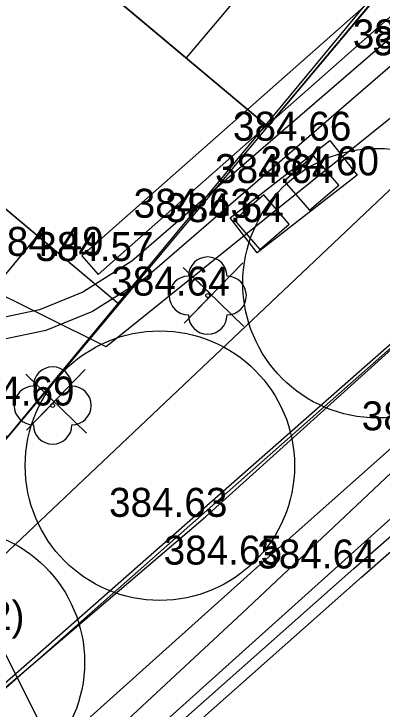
# Model space of a CAD drawing. Extents: x -438233 to -437334, y -1133133 to -1132623.
# Drawn here: x -438075.74 to -438066.2, y -1133013.03 to -1132995.04 of the extents above; entities that cross this region are included whole.
import ezdxf

# ---------------------------------------------------------------- set-up
doc = ezdxf.new("R2010")
doc.units = 0
for name, color, linetype in [('Vrstva 1', 7, 'Continuous'), ('Vrstva 10', 7, 'Continuous'), ('Vrstva 11', 7, 'Continuous'), ('Vrstva 22', 7, 'Continuous'), ('Vrstva 26', 7, 'Continuous'), ('Vrstva 3', 7, 'Continuous'), ('Vrstva 40', 7, 'Continuous'), ('Vrstva 50', 7, 'Continuous'), ('Vrstva 53', 7, 'Continuous'), ('Vrstva 55', 7, 'Continuous'), ('Vrstva 7', 7, 'Continuous'), ('Vrstva 9', 7, 'Continuous')]:
    doc.layers.add(name, color=color, linetype=linetype)

msp = doc.modelspace()

# ---------------------------------------------------------------- linework, layer by layer
at = {"layer": 'Vrstva 1'}
for p, q in [((-438094.467, -1132976.751), (-438069.171, -1132997.943)), ((-438098.32, -1132981.35), (-438073.024, -1133002.543)), ((-438068.389, -1132992.728), (-438071.279, -1132996.177)), ((-438066.287, -1132994.502), (-438076.556, -1133006.759)), ((-438067.569, -1132998.318), (-438067.569, -1132998.318)), ((-438066.854, -1132999.215), (-438066.854, -1132999.215)), ((-438068.034, -1132999.416), (-438068.034, -1132999.416)), ((-438070.142, -1133000.313), (-438070.142, -1133000.313)), ((-438069.32, -1133000.427), (-438069.32, -1133000.427)), ((-438075.132, -1133000.777), (-438078.022, -1133004.226)), ((-438073.986, -1133001.3), (-438073.986, -1133001.3)), ((-438072.69, -1133001.433), (-438072.69, -1133001.433)), ((-438070.722, -1133002.328), (-438070.722, -1133002.328)), ((-438074.741, -1133005.174), (-438074.741, -1133005.174)), ((-438070.78, -1133008.056), (-438070.78, -1133008.056)), ((-438069.364, -1133009.292), (-438069.364, -1133009.292)), ((-438066.939, -1133009.393), (-438066.939, -1133009.393))]:
    msp.add_line(p, q, dxfattribs=at)
at = {"layer": 'Vrstva 10'}
msp.add_lwpolyline([(-438035.457, -1132968.667), (-438040.579, -1132973.124), (-438048.857, -1132980.452), (-438065.053, -1132994.849), (-438072.69, -1133001.433), (-438073.961, -1133002.24), (-438075.077, -1133002.697), (-438076.272, -1133002.948)], dxfattribs=at)
at = {"layer": 'Vrstva 11'}
for points in [[(-438079.851, -1133001.541), (-438081.143, -1133003.836), (-438082.651, -1133014.98), (-438080.295, -1133016.157), (-438070.78, -1133008.056), (-438059.123, -1132997.555), (-438044.087, -1132984.346), (-438028.394, -1132970.577), (-438016.298, -1132960.009), (-438006.567, -1132951.363)], [(-438080.927, -1133019.451), (-438077.139, -1133016.254), (-438069.364, -1133009.292), (-438057.759, -1132998.987), (-438043.045, -1132985.96), (-438027.231, -1132972.034), (-438013.435, -1132960.019)], [(-438073.986, -1133001.3), (-438049.447, -1132979.638), (-438041.292, -1132972.525), (-438035.024, -1132966.82)], [(-438073.562, -1133001.78), (-438065.335, -1132994.517)], [(-438073.986, -1133001.3), (-438073.562, -1133001.78)]]:
    msp.add_lwpolyline(points, dxfattribs=at)
msp.add_lwpolyline([(-438070.142, -1133000.313), (-438067.557, -1132998.309), (-438066.854, -1132999.215), (-438069.439, -1133001.219)], close=True, dxfattribs=at)
at = {"layer": 'Vrstva 22'}
for centre in [(-438070.722, -1133002.328), (-438074.741, -1133005.174)]:
    msp.add_circle(centre, 0.05, dxfattribs=at)
for centre, start, end in [((-438070.722, -1133001.828), 0, 180), ((-438071.222, -1133002.328), 90, 270), ((-438070.222, -1133002.328), 270, 90), ((-438070.722, -1133002.828), 180, 0), ((-438074.741, -1133004.674), 0, 180), ((-438075.241, -1133005.174), 90, 270), ((-438074.241, -1133005.174), 270, 90), ((-438074.741, -1133005.674), 180, 0)]:
    msp.add_arc(centre, 0.5, start, end, dxfattribs=at)
at = {"layer": 'Vrstva 26'}
for points in [[(-438067.982, -1132998.711), (-438068.739, -1132999.364), (-438068.086, -1133000.121), (-438067.329, -1132999.468)], [(-438069.268, -1132999.722), (-438070.025, -1133000.375), (-438069.372, -1133001.132), (-438068.615, -1133000.479)]]:
    msp.add_lwpolyline(points, close=True, dxfattribs=at)
at = {"layer": 'Vrstva 40'}
for points in [[(-438006.567, -1132951.363), (-438080.295, -1133016.157), (-438085.207, -1133012.071), (-438080.546, -1133006.803), (-438077.182, -1133006.231), (-438076.556, -1133006.759), (-438075.914, -1133005.992), (-438066.402, -1132994.506), (-438073.034, -1132988.817), (-438072.353, -1132988.023), (-438069.665, -1132990.252), (-438068.287, -1132988.606), (-438065.604, -1132990.854), (-438063.799, -1132988.701), (-438061.117, -1132990.948), (-438050.796, -1132978.629), (-438047.72, -1132977.59), (-438045.204, -1132976.394), (-438042.678, -1132974.884), (-438040.928, -1132973.634), (-438039.59, -1132972.514), (-438037.876, -1132970.87), (-438035.397, -1132967.806), (-438020.007, -1132954.124)], [(-438069.816, -1133001.479), (-438071.336, -1133003.045), (-438070.625, -1133002.312), (-438071.358, -1133001.601), (-438069.785, -1133003.126)], [(-438073.895, -1133004.243), (-438075.415, -1133005.81), (-438074.704, -1133005.077), (-438075.437, -1133004.366), (-438073.864, -1133005.891)]]:
    msp.add_lwpolyline(points, dxfattribs=at)
for centre in [(-438066.325, -1133002.007), (-438071.963, -1133006.731), (-438077.403, -1133011.819)]:
    msp.add_circle(centre, 3.489, dxfattribs=at)
at = {"layer": 'Vrstva 50'}
for points in [[(-438091.577, -1132973.302), (-438066.273, -1132994.5), (-438069.163, -1132997.95), (-438094.467, -1132976.751)], [(-438098.32, -1132981.35), (-438073.025, -1133002.541), (-438075.915, -1133005.991), (-438101.21, -1132984.8)]]:
    msp.add_lwpolyline(points, close=True, dxfattribs=at)
at = {"layer": 'Vrstva 53'}
for points in [[(-438082.34, -1133022.27), (-438082.4, -1133022.17), (-438081.23, -1133020.54), (-438076.87, -1133017.08), (-438069.83, -1133010.55), (-438064.49, -1133005.53), (-438059.58, -1133001.78), (-438053.45, -1132996.74), (-438044, -1132988.47), (-438035.57, -1132981.06), (-438029.47, -1132975.65), (-438020.01, -1132967.31), (-438013.46, -1132961.68), (-438012.29, -1132959.83), (-438009.79, -1132957.66), (-438009.76, -1132957.6), (-438007.47, -1132956.33), (-438007.65, -1132955.49), (-438008.56, -1132952.65)], [(-438080.228, -1133025.09), (-438082.04, -1133022.81), (-438081.87, -1133021.95), (-438073.76, -1133015.09), (-438028.25, -1132974.2), (-438011.87, -1132960.69), (-438014.77, -1132957.4)]]:
    msp.add_lwpolyline(points, dxfattribs=at)
at = {"layer": 'Vrstva 55'}
for points in [[(-437982.978, -1132924.484), (-438038.365, -1132973.439), (-438076.856, -1133009.846)], [(-438074.959, -1133013.61), (-438076.856, -1133009.846), (-438083.298, -1132998.719), (-438115.192, -1132972.054), (-438146.469, -1132953.711), (-438176.9, -1132931.48)], [(-437979.821, -1132940.76), (-437988.363, -1132937.437), (-438041.643, -1132982.184), (-438086.636, -1133021.919)], [(-438063.956, -1132996.108), (-438073.354, -1133003.651), (-438083.298, -1132998.719)]]:
    msp.add_lwpolyline(points, dxfattribs=at)
at = {"layer": 'Vrstva 7'}
for points in [[(-438075.11, -1133016.633), (-438066.939, -1133009.393), (-438057.287, -1133000.946), (-438041.953, -1132987.39), (-438025.485, -1132972.915), (-438016.315, -1132964.831), (-438000.869, -1132951.177), (-437989.371, -1132943.616), (-437973.864, -1132938.609), (-437972.742, -1132939.048)], [(-438074.911, -1133016.858), (-438066.741, -1133009.618), (-438057.089, -1133001.171), (-438041.755, -1132987.615), (-438025.287, -1132973.14), (-438016.116, -1132965.056), (-438000.686, -1132951.416), (-437989.24, -1132943.889), (-437973.874, -1132938.927), (-437973.053, -1132939.248)]]:
    msp.add_lwpolyline(points, dxfattribs=at)
at = {"layer": 'Vrstva 9'}
msp.add_lwpolyline([(-438065.425, -1132995.907), (-438072.356, -1133001.882), (-438073.704, -1133002.738), (-438074.913, -1133003.233), (-438076.157, -1133003.494)], dxfattribs=at)

# ---------------------------------------------------------------- texts
at = {"layer": 'Vrstva 3'}
for s, p in [('384.59 ', (-438066.964, -1132995.93)), ('383.51 ', (-438066.456, -1132996.108)), ('384.66 ', (-438070.069, -1132998.318)), ('384.60 ', (-438069.354, -1132999.215)), ('384.64 ', (-438070.534, -1132999.416)), ('384.63 ', (-438072.642, -1133000.313)), ('384.64 ', (-438071.82, -1133000.427)), ('384.49 ', (-438076.486, -1133001.3)), ('384.57 ', (-438075.19, -1133001.433)), ('384.64 ', (-438073.222, -1133002.328)), ('384.69 ', (-438077.241, -1133005.174)), ('384.72 ', (-438066.733, -1133005.816)), ('384.63 ', (-438073.28, -1133008.056)), ('384.65 ', (-438071.864, -1133009.292)), ('384.64 ', (-438069.439, -1133009.393))]:
    msp.add_text(s, height=0.75, dxfattribs=at).set_placement(p)
at = {"layer": 'Vrstva 55'}
msp.add_text('(382 42) ', height=0.75, dxfattribs=at).set_placement((-438079.207, -1133010.983))

doc.saveas('drawing.dxf')
